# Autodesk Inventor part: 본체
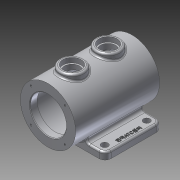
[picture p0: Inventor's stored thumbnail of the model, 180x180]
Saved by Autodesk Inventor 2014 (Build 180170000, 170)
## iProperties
Created: 2014-12
Part Number: 본체
Material: 알루미늄 6061
Document SubType Name: Modeling
Designer: Owner
Density: 2.71 g/cm^3
Appearance: 알루미늄 - 평지
Mass: 1281.45 g
Surface Area: 1027.89 cm^2
Volume: 472.861 cm^3
Author: Owner
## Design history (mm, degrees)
sketch "스케치1"
  geometry: C1 r 46 at (0, 0); 1 further point
  constraints: 1 centre point, 1 coincident
  dimensions: "d0" = 92 diameter of C1
extrude "돌출1" new body sketch "스케치1" stored distance "d1" = 140; taper "d2" = 0 deg
node "작업 평면1"
sketch "스케치2"
  geometry: L1 (65, -38)-(65, -50); L2 (65, -50)-(-65, -50); L3 (-65, -50)-(-65, -38); L4 (-65, -38)-(-25.923, -38); L5 (25.923, -38)-(65, -38); A1 r 46 centre (0, 0) between (-25.923, -38) and (25.923, -38) reference; 5 further points
  constraints: 10 end point, 3 midpoint, 3 parallel, 2 horizontal, 2 perpendicular, 2 point on circle, 2 vertical alignment, 1 horizontal alignment
  dimensions: "d4" = 130 distance of L3.end L1.start; "d5" = 12 distance of L1.start L1.end; "d6" = 50 distance from line of L2 point (0, 0)
extrude "돌출2" join sketch "스케치2" distance "d7" = 95; taper "d8" = 0 deg
sketch "스케치3"
  geometry: C1 r 46 at (0, 0) reference; C2 r 30 at (0, 0)
  constraints: 1 centre point, 1 coincident
  dimensions: "d9" = 60 diameter of C2
extrude "돌출3" cut sketch "스케치3" distance "d10" = 12; taper "d11" = 0 deg
sketch "스케치4"
  geometry: C1 r 30 at (0, 0) reference; C2 r 37.5 at (0, 0)
  constraints: 1 centre point, 1 coincident
  dimensions: "d12" = 75 diameter of C2
extrude "돌출4" cut sketch "스케치4" distance "d13" = 116; taper "d14" = 0 deg
node "작업 평면2"
sketch "스케치8"
  geometry: L1 (39.077, 0)-(0, 0) reference; C1 r 5.5 at (26.077, 12.5); 1 further point
  constraints: 1 centre point
  dimensions: "d26" = 11 diameter of C1; "d27" = 52 horizontal distance of C1.centre point (-25.923, 40); "d28" = 12.5 distance from line of L1 C1.centre
extrude "돌출8" cut sketch "스케치8" stored distance "d29" = 8; taper "d30" = 0 deg
sketch "스케치9"
  geometry: L1 (0, 95)-(39.077, 95) reference; C1 r 5.5 at (26.077, 12.5) reference; C2 r 5.5 at (26.077, 82.5); 1 further point
  constraints: 1 centre point, 1 vertical alignment
  dimensions: "d31" = 11 diameter of C2; "d32" = 12.5 distance from line of L1 C2.centre
extrude "돌출9" cut sketch "스케치9" stored distance "d33" = 8; taper "d34" = 0 deg
sketch "스케치10"
  geometry: L1 (0, 0)-(28.284, 28.284); L2 (0, 0)-(40, 0); C1 r 46 at (0, 0) reference; 1 further point
  constraints: 4 end point, 1 coincident, 1 equal length, 1 horizontal
  dimensions: "d35" = 40 distance of L1.start L1.end; "d36" = 45 deg angle of L2 L1
hole "구멍1" sketch "스케치10" at (28.284, 28.284) diameter "d37" = 3.242; stored, may be unused: countersink angle "d41" = 90 deg, drill point angle "d43" = 118 deg; dims "d38" = 8, "d39" = 4, "d40" = 2, "d42" = 10
fillet "모깎기1" dims "d47" = 5
fillet "모깎기2" dims "d48" = 10
fillet "모깎기3" dims "d49" = 3
fillet "모깎기5" dims "d51" = 3
chamfer "모따기1" distance "d52" = 1; stored, may be unused: second distance "d53" = 2, angle "d54" = 45 deg
sketch "스케치11"
  geometry: L1 (23.116, -7)-(23.116, -82) reference; L2 (26.116, -82)-(26.116, -7) reference; 3 further points
  constraints: 1 horizontal alignment, 1 midpoint, 1 other
  dimensions: "d55" = 8 distance from line of L2 point (18.116, -44.5)
feature "엠보싱1" sketch "스케치11" dims "d1" = 140, "d9" = 60, "d56" = 1, "d57" = 0
node "작업 평면3"
sketch "스케치13"
  geometry: L1 (-46, -70)-(46, -70) reference; C1 r 20 at (0, -30); 1 further point
  constraints: 1 centre point, 1 vertical alignment
  dimensions: "d59" = 40 diameter of C1; "d60" = 40 distance from line of L1 C1.centre
extrude "돌출10" join sketch "스케치13" stored distance "d61" = 10; taper "d62" = 0 deg
sketch "스케치14"
  geometry: C1 r 20 at (0, 0) reference; C2 r 15 at (0, 0); 1 further point
  constraints: 1 centre point, 1 coincident
  dimensions: "d63" = 30 diameter of C2
extrude "돌출11" cut sketch "스케치14" distance "d64" = 8; taper "d65" = 0 deg
sketch "스케치15"
  geometry: C1 r 15 at (0, 0) reference; C2 r 12.5 at (0, 0); 1 further point
  constraints: 1 centre point, 1 coincident
  dimensions: "d66" = 25 diameter of C2
extrude "돌출12" cut sketch "스케치15" stored distance "d67" = 8; taper "d68" = 0 deg
fillet "모깎기6" dims "d69" = 3
fillet "모깎기7" dims "d70" = 3
node "솔리드1"
mirror "대칭1"
mirror "대칭3"
pattern_circular "원형 패턴1" dims angle "d45" = 360 deg
mirror "대칭4"
mirror "대칭5"
node "투영된 루프1"
other parameters: "d15" = 53, "d58" = 53
